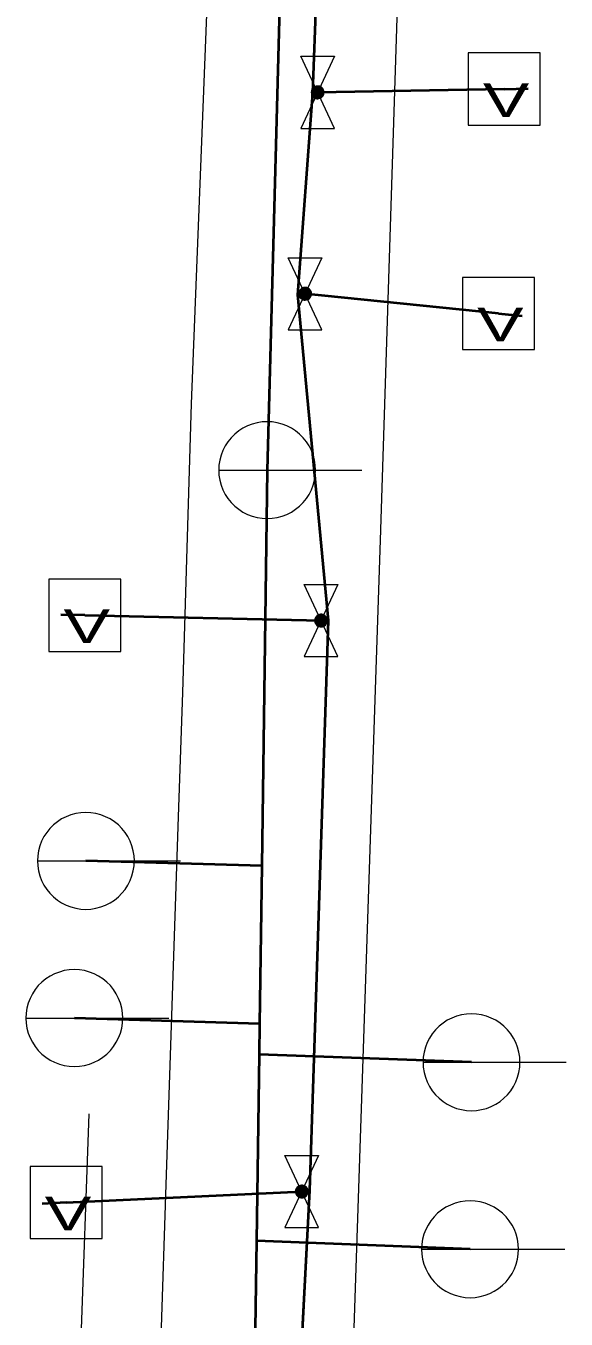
# Model space of a CAD drawing. Extents: x -968691 to -140888, y -1376050 to -879856.
# Drawn here: x -646122.08 to -646110.84, y -1062475.84 to -1062448.94 of the extents above; entities that cross this region are included whole.
import ezdxf
from ezdxf.enums import TextEntityAlignment as Align

# ---------------------------------------------------------------- set-up
doc = ezdxf.new("R2010")
doc.units = 0
doc.header["$LTSCALE"] = 4.8
doc.linetypes.add('DOTTED', pattern=[1.5, 0.3, -1.2])
doc.linetypes.add('LONG_DASHED', pattern=[7.5, 6, -1.5])
doc.layers.add('1', color=7, linetype='Continuous', lineweight=13)

msp = doc.modelspace()

# ---------------------------------------------------------------- hatches: boundary and pattern name
at = {"layer": '1'}
for points in [[(-646115.878, -1062450.32), (-646115.88, -1062450.296), (-646115.887, -1062450.273), (-646115.897, -1062450.251), (-646115.911, -1062450.232), (-646115.929, -1062450.215), (-646115.949, -1062450.202), (-646115.972, -1062450.193), (-646115.995, -1062450.189), (-646116.019, -1062450.188), (-646116.043, -1062450.192), (-646116.066, -1062450.2), (-646116.087, -1062450.212), (-646116.105, -1062450.228), (-646116.12, -1062450.247), (-646116.132, -1062450.268), (-646116.139, -1062450.291), (-646116.142, -1062450.315), (-646116.141, -1062450.339), (-646116.135, -1062450.362), (-646116.125, -1062450.384), (-646116.112, -1062450.404), (-646116.095, -1062450.421), (-646116.075, -1062450.435), (-646116.053, -1062450.445), (-646116.03, -1062450.451), (-646116.006, -1062450.452), (-646115.982, -1062450.449), (-646115.959, -1062450.442), (-646115.938, -1062450.431), (-646115.919, -1062450.416), (-646115.903, -1062450.397), (-646115.891, -1062450.377), (-646115.882, -1062450.354), (-646115.878, -1062450.33)], [(-646116.138, -1062454.51), (-646116.14, -1062454.486), (-646116.147, -1062454.463), (-646116.157, -1062454.441), (-646116.171, -1062454.422), (-646116.189, -1062454.405), (-646116.209, -1062454.392), (-646116.232, -1062454.383), (-646116.255, -1062454.379), (-646116.279, -1062454.378), (-646116.303, -1062454.382), (-646116.326, -1062454.39), (-646116.347, -1062454.402), (-646116.365, -1062454.418), (-646116.38, -1062454.437), (-646116.392, -1062454.458), (-646116.399, -1062454.481), (-646116.402, -1062454.505), (-646116.401, -1062454.529), (-646116.395, -1062454.552), (-646116.385, -1062454.574), (-646116.372, -1062454.594), (-646116.355, -1062454.611), (-646116.335, -1062454.625), (-646116.313, -1062454.635), (-646116.29, -1062454.641), (-646116.266, -1062454.642), (-646116.242, -1062454.639), (-646116.219, -1062454.632), (-646116.198, -1062454.621), (-646116.179, -1062454.606), (-646116.163, -1062454.587), (-646116.151, -1062454.567), (-646116.142, -1062454.544), (-646116.138, -1062454.52)], [(-646115.808, -1062461.31), (-646115.81, -1062461.286), (-646115.817, -1062461.263), (-646115.827, -1062461.241), (-646115.841, -1062461.222), (-646115.859, -1062461.205), (-646115.879, -1062461.192), (-646115.902, -1062461.183), (-646115.925, -1062461.179), (-646115.949, -1062461.178), (-646115.973, -1062461.182), (-646115.996, -1062461.19), (-646116.017, -1062461.202), (-646116.035, -1062461.218), (-646116.05, -1062461.237), (-646116.062, -1062461.258), (-646116.069, -1062461.281), (-646116.072, -1062461.305), (-646116.071, -1062461.329), (-646116.065, -1062461.352), (-646116.055, -1062461.374), (-646116.042, -1062461.394), (-646116.025, -1062461.411), (-646116.005, -1062461.425), (-646115.983, -1062461.435), (-646115.96, -1062461.441), (-646115.936, -1062461.442), (-646115.912, -1062461.439), (-646115.889, -1062461.432), (-646115.868, -1062461.421), (-646115.849, -1062461.406), (-646115.833, -1062461.387), (-646115.821, -1062461.367), (-646115.812, -1062461.344), (-646115.808, -1062461.32)], [(-646116.208, -1062473.19), (-646116.21, -1062473.166), (-646116.217, -1062473.143), (-646116.227, -1062473.121), (-646116.241, -1062473.102), (-646116.259, -1062473.085), (-646116.279, -1062473.072), (-646116.302, -1062473.063), (-646116.325, -1062473.059), (-646116.349, -1062473.058), (-646116.373, -1062473.062), (-646116.396, -1062473.07), (-646116.417, -1062473.082), (-646116.435, -1062473.098), (-646116.45, -1062473.117), (-646116.462, -1062473.138), (-646116.469, -1062473.161), (-646116.472, -1062473.185), (-646116.471, -1062473.209), (-646116.465, -1062473.232), (-646116.455, -1062473.254), (-646116.442, -1062473.274), (-646116.425, -1062473.291), (-646116.405, -1062473.305), (-646116.383, -1062473.315), (-646116.36, -1062473.321), (-646116.336, -1062473.322), (-646116.312, -1062473.319), (-646116.289, -1062473.312), (-646116.268, -1062473.301), (-646116.249, -1062473.286), (-646116.233, -1062473.267), (-646116.221, -1062473.247), (-646116.212, -1062473.224), (-646116.208, -1062473.2)]]:
    msp.add_hatch(color=256, dxfattribs=at).paths.add_polyline_path(points)

# ---------------------------------------------------------------- linework, layer by layer
at = {"layer": '1', "linetype": 'LONG_DASHED', "lineweight": 40}
for p, q in [((-646115.47, -1062433.81), (-646116.12, -1062450.33)), ((-646116.12, -1062450.33), (-646116.43, -1062454.53)), ((-646116.12, -1062450.33), (-646116.01, -1062450.32)), ((-646112.13, -1062450.25), (-646116.01, -1062450.32)), ((-646116.43, -1062454.53), (-646116.27, -1062454.51)), ((-646116.43, -1062454.53), (-646115.79, -1062461.31)), ((-646112.25, -1062454.92), (-646116.27, -1062454.51)), ((-646120.85, -1062461.2), (-646115.94, -1062461.31)), ((-646115.79, -1062461.31), (-646116.18, -1062473.17)), ((-646115.94, -1062461.31), (-646115.79, -1062461.31)), ((-646117.174, -1062466.412), (-646120.83, -1062466.31)), ((-646117.219, -1062469.7), (-646121.07, -1062469.58)), ((-646112.81, -1062470.5), (-646117.228, -1062470.338)), ((-646121.24, -1062473.42), (-646116.34, -1062473.19)), ((-646116.18, -1062473.17), (-646116.77, -1062484.57)), ((-646116.18, -1062473.17), (-646116.34, -1062473.19)), ((-646112.84, -1062474.39), (-646117.282, -1062474.217))]:
    msp.add_line(p, q, dxfattribs=at)
at = {"layer": '1', "lineweight": 35}
for p, q in [((-646115.47, -1062433.81), (-646116.12, -1062450.33)), ((-646116.12, -1062450.33), (-646116.43, -1062454.53)), ((-646116.43, -1062454.53), (-646115.79, -1062461.31)), ((-646115.79, -1062461.31), (-646116.18, -1062473.17)), ((-646116.18, -1062473.17), (-646116.77, -1062484.57))]:
    msp.add_line(p, q, dxfattribs=at)
at = {"layer": '1'}
for p, q in [((-646118.635, -1062456.797), (-646118.301, -1062448.324)), ((-646116.12, -1062450.33), (-646116.01, -1062450.32)), ((-646112.13, -1062450.25), (-646116.01, -1062450.32)), ((-646112.13, -1062450.25), (-646111.63, -1062450.241)), ((-646116.43, -1062454.53), (-646116.27, -1062454.51)), ((-646112.25, -1062454.92), (-646116.27, -1062454.51)), ((-646112.25, -1062454.92), (-646111.753, -1062454.971)), ((-646118.811, -1062462.804), (-646118.635, -1062456.797)), ((-646118.068, -1062458.18), (-646115.092, -1062458.18)), ((-646114.71, -1062459.64), (-646115.51, -1062483.63)), ((-646120.85, -1062461.2), (-646121.35, -1062461.189)), ((-646120.85, -1062461.2), (-646115.94, -1062461.31)), ((-646115.94, -1062461.31), (-646115.79, -1062461.31)), ((-646118.906, -1062465.392), (-646118.811, -1062462.804)), ((-646119.153, -1062472.835), (-646118.906, -1062465.392)), ((-646121.838, -1062466.31), (-646118.862, -1062466.31)), ((-646117.174, -1062466.412), (-646120.83, -1062466.31)), ((-646122.078, -1062469.58), (-646119.102, -1062469.58)), ((-646117.219, -1062469.7), (-646121.07, -1062469.58)), ((-646112.81, -1062470.5), (-646117.228, -1062470.338)), ((-646113.818, -1062470.5), (-646110.842, -1062470.5)), ((-646120.769, -1062471.574), (-646121.569, -1062494.426)), ((-646119.77, -1062491.16), (-646119.153, -1062472.835)), ((-646121.24, -1062473.42), (-646116.34, -1062473.19)), ((-646116.18, -1062473.17), (-646116.34, -1062473.19)), ((-646121.24, -1062473.42), (-646121.739, -1062473.443)), ((-646112.84, -1062474.39), (-646117.282, -1062474.217)), ((-646113.848, -1062474.39), (-646110.872, -1062474.39))]:
    msp.add_line(p, q, dxfattribs=at)
at = {"layer": '1', "linetype": 'DOTTED', "lineweight": 40}
for p, q in [((-646112.13, -1062450.25), (-646111.63, -1062450.241)), ((-646112.25, -1062454.92), (-646111.753, -1062454.971)), ((-646120.85, -1062461.2), (-646121.35, -1062461.189)), ((-646121.24, -1062473.42), (-646121.739, -1062473.443))]:
    msp.add_line(p, q, dxfattribs=at)
at = {"layer": '1'}
msp.add_lwpolyline([(-646113.81, -1062431.66), (-646114.114, -1062440.939), (-646114.71, -1062459.64)], dxfattribs=at)
at = {"layer": '1', "linetype": 'LONG_DASHED', "lineweight": 40}
for points in [[(-646116.721, -1062445.47), (-646117.06, -1062458.18), (-646117.174, -1062466.412), (-646117.219, -1062469.7), (-646117.228, -1062470.338), (-646117.282, -1062474.217)], [(-646117.282, -1062474.217), (-646117.5, -1062490), (-646113.72, -1062489.86)]]:
    msp.add_lwpolyline(points, dxfattribs=at)
at = {"layer": '1', "lineweight": 35}
for points in [[(-646116.721, -1062445.47), (-646117.06, -1062458.18), (-646117.174, -1062466.412), (-646117.219, -1062469.7), (-646117.228, -1062470.338), (-646117.282, -1062474.217)], [(-646117.282, -1062474.217), (-646117.5, -1062490), (-646113.72, -1062489.86)]]:
    msp.add_lwpolyline(points, dxfattribs=at)
at = {"layer": '1'}
for points in [[(-646116.36, -1062449.57), (-646115.66, -1062449.57), (-646116.36, -1062451.07), (-646115.66, -1062451.07)], [(-646112.88, -1062451), (-646111.38, -1062451), (-646111.38, -1062449.5), (-646112.88, -1062449.5)], [(-646115.878, -1062450.32), (-646115.88, -1062450.296), (-646115.887, -1062450.273), (-646115.897, -1062450.251), (-646115.911, -1062450.232), (-646115.929, -1062450.215), (-646115.949, -1062450.202), (-646115.972, -1062450.193), (-646115.995, -1062450.189), (-646116.019, -1062450.188), (-646116.043, -1062450.192), (-646116.066, -1062450.2), (-646116.087, -1062450.212), (-646116.105, -1062450.228), (-646116.12, -1062450.247), (-646116.132, -1062450.268), (-646116.139, -1062450.291), (-646116.142, -1062450.315), (-646116.141, -1062450.339), (-646116.135, -1062450.362), (-646116.125, -1062450.384), (-646116.112, -1062450.404), (-646116.095, -1062450.421), (-646116.075, -1062450.435), (-646116.053, -1062450.445), (-646116.03, -1062450.451), (-646116.006, -1062450.452), (-646115.982, -1062450.449), (-646115.959, -1062450.442), (-646115.938, -1062450.431), (-646115.919, -1062450.416), (-646115.903, -1062450.397), (-646115.891, -1062450.377), (-646115.882, -1062450.354), (-646115.878, -1062450.33)], [(-646116.62, -1062453.76), (-646115.92, -1062453.76), (-646116.62, -1062455.26), (-646115.92, -1062455.26)], [(-646113, -1062455.67), (-646111.5, -1062455.67), (-646111.5, -1062454.17), (-646113, -1062454.17)], [(-646116.138, -1062454.51), (-646116.14, -1062454.486), (-646116.147, -1062454.463), (-646116.157, -1062454.441), (-646116.171, -1062454.422), (-646116.189, -1062454.405), (-646116.209, -1062454.392), (-646116.232, -1062454.383), (-646116.255, -1062454.379), (-646116.279, -1062454.378), (-646116.303, -1062454.382), (-646116.326, -1062454.39), (-646116.347, -1062454.402), (-646116.365, -1062454.418), (-646116.38, -1062454.437), (-646116.392, -1062454.458), (-646116.399, -1062454.481), (-646116.402, -1062454.505), (-646116.401, -1062454.529), (-646116.395, -1062454.552), (-646116.385, -1062454.574), (-646116.372, -1062454.594), (-646116.355, -1062454.611), (-646116.335, -1062454.625), (-646116.313, -1062454.635), (-646116.29, -1062454.641), (-646116.266, -1062454.642), (-646116.242, -1062454.639), (-646116.219, -1062454.632), (-646116.198, -1062454.621), (-646116.179, -1062454.606), (-646116.163, -1062454.587), (-646116.151, -1062454.567), (-646116.142, -1062454.544), (-646116.138, -1062454.52)], [(-646117.06, -1062457.172), (-646117.165, -1062457.178), (-646117.269, -1062457.194), (-646117.371, -1062457.222), (-646117.47, -1062457.26), (-646117.564, -1062457.307), (-646117.652, -1062457.365), (-646117.734, -1062457.431), (-646117.809, -1062457.506), (-646117.875, -1062457.588), (-646117.933, -1062457.676), (-646117.98, -1062457.77), (-646118.018, -1062457.869), (-646118.046, -1062457.971), (-646118.062, -1062458.075), (-646118.068, -1062458.18), (-646118.062, -1062458.285), (-646118.046, -1062458.39), (-646118.018, -1062458.492), (-646117.98, -1062458.59), (-646117.933, -1062458.684), (-646117.875, -1062458.773), (-646117.809, -1062458.855), (-646117.734, -1062458.929), (-646117.652, -1062458.995), (-646117.564, -1062459.053), (-646117.47, -1062459.101), (-646117.371, -1062459.139), (-646117.269, -1062459.166), (-646117.165, -1062459.182), (-646117.06, -1062459.188), (-646116.955, -1062459.182), (-646116.85, -1062459.166), (-646116.748, -1062459.139), (-646116.65, -1062459.101), (-646116.556, -1062459.053), (-646116.467, -1062458.995), (-646116.385, -1062458.929), (-646116.311, -1062458.855), (-646116.245, -1062458.773), (-646116.187, -1062458.684), (-646116.139, -1062458.59), (-646116.101, -1062458.492), (-646116.074, -1062458.39), (-646116.058, -1062458.285), (-646116.052, -1062458.18), (-646116.058, -1062458.075), (-646116.074, -1062457.971), (-646116.101, -1062457.869), (-646116.139, -1062457.77), (-646116.187, -1062457.676), (-646116.245, -1062457.588), (-646116.311, -1062457.506), (-646116.385, -1062457.431), (-646116.467, -1062457.365), (-646116.556, -1062457.307), (-646116.65, -1062457.26), (-646116.748, -1062457.222), (-646116.85, -1062457.194), (-646116.955, -1062457.178)], [(-646121.6, -1062461.95), (-646120.1, -1062461.95), (-646120.1, -1062460.45), (-646121.6, -1062460.45)], [(-646116.29, -1062460.56), (-646115.59, -1062460.56), (-646116.29, -1062462.06), (-646115.59, -1062462.06)], [(-646115.808, -1062461.31), (-646115.81, -1062461.286), (-646115.817, -1062461.263), (-646115.827, -1062461.241), (-646115.841, -1062461.222), (-646115.859, -1062461.205), (-646115.879, -1062461.192), (-646115.902, -1062461.183), (-646115.925, -1062461.179), (-646115.949, -1062461.178), (-646115.973, -1062461.182), (-646115.996, -1062461.19), (-646116.017, -1062461.202), (-646116.035, -1062461.218), (-646116.05, -1062461.237), (-646116.062, -1062461.258), (-646116.069, -1062461.281), (-646116.072, -1062461.305), (-646116.071, -1062461.329), (-646116.065, -1062461.352), (-646116.055, -1062461.374), (-646116.042, -1062461.394), (-646116.025, -1062461.411), (-646116.005, -1062461.425), (-646115.983, -1062461.435), (-646115.96, -1062461.441), (-646115.936, -1062461.442), (-646115.912, -1062461.439), (-646115.889, -1062461.432), (-646115.868, -1062461.421), (-646115.849, -1062461.406), (-646115.833, -1062461.387), (-646115.821, -1062461.367), (-646115.812, -1062461.344), (-646115.808, -1062461.32)], [(-646120.83, -1062465.302), (-646120.935, -1062465.308), (-646121.039, -1062465.324), (-646121.141, -1062465.352), (-646121.24, -1062465.39), (-646121.334, -1062465.437), (-646121.422, -1062465.495), (-646121.504, -1062465.561), (-646121.579, -1062465.636), (-646121.645, -1062465.718), (-646121.703, -1062465.806), (-646121.75, -1062465.9), (-646121.788, -1062465.999), (-646121.816, -1062466.101), (-646121.832, -1062466.205), (-646121.838, -1062466.31), (-646121.832, -1062466.415), (-646121.816, -1062466.52), (-646121.788, -1062466.622), (-646121.75, -1062466.72), (-646121.703, -1062466.814), (-646121.645, -1062466.903), (-646121.579, -1062466.985), (-646121.504, -1062467.059), (-646121.422, -1062467.125), (-646121.334, -1062467.183), (-646121.24, -1062467.231), (-646121.141, -1062467.269), (-646121.039, -1062467.296), (-646120.935, -1062467.312), (-646120.83, -1062467.318), (-646120.725, -1062467.312), (-646120.62, -1062467.296), (-646120.518, -1062467.269), (-646120.42, -1062467.231), (-646120.326, -1062467.183), (-646120.237, -1062467.125), (-646120.155, -1062467.059), (-646120.081, -1062466.985), (-646120.015, -1062466.903), (-646119.957, -1062466.814), (-646119.909, -1062466.72), (-646119.871, -1062466.622), (-646119.844, -1062466.52), (-646119.828, -1062466.415), (-646119.822, -1062466.31), (-646119.828, -1062466.205), (-646119.844, -1062466.101), (-646119.871, -1062465.999), (-646119.909, -1062465.9), (-646119.957, -1062465.806), (-646120.015, -1062465.718), (-646120.081, -1062465.636), (-646120.155, -1062465.561), (-646120.237, -1062465.495), (-646120.326, -1062465.437), (-646120.42, -1062465.39), (-646120.518, -1062465.352), (-646120.62, -1062465.324), (-646120.725, -1062465.308)], [(-646121.07, -1062468.572), (-646121.175, -1062468.578), (-646121.279, -1062468.594), (-646121.381, -1062468.622), (-646121.48, -1062468.66), (-646121.574, -1062468.707), (-646121.662, -1062468.765), (-646121.744, -1062468.831), (-646121.819, -1062468.906), (-646121.885, -1062468.988), (-646121.943, -1062469.076), (-646121.99, -1062469.17), (-646122.028, -1062469.269), (-646122.056, -1062469.371), (-646122.072, -1062469.475), (-646122.078, -1062469.58), (-646122.072, -1062469.685), (-646122.056, -1062469.79), (-646122.028, -1062469.892), (-646121.99, -1062469.99), (-646121.943, -1062470.084), (-646121.885, -1062470.173), (-646121.819, -1062470.255), (-646121.744, -1062470.329), (-646121.662, -1062470.395), (-646121.574, -1062470.453), (-646121.48, -1062470.501), (-646121.381, -1062470.539), (-646121.279, -1062470.566), (-646121.175, -1062470.582), (-646121.07, -1062470.588), (-646120.965, -1062470.582), (-646120.86, -1062470.566), (-646120.758, -1062470.539), (-646120.66, -1062470.501), (-646120.566, -1062470.453), (-646120.477, -1062470.395), (-646120.395, -1062470.329), (-646120.321, -1062470.255), (-646120.255, -1062470.173), (-646120.197, -1062470.084), (-646120.149, -1062469.99), (-646120.111, -1062469.892), (-646120.084, -1062469.79), (-646120.068, -1062469.685), (-646120.062, -1062469.58), (-646120.068, -1062469.475), (-646120.084, -1062469.371), (-646120.111, -1062469.269), (-646120.149, -1062469.17), (-646120.197, -1062469.076), (-646120.255, -1062468.988), (-646120.321, -1062468.906), (-646120.395, -1062468.831), (-646120.477, -1062468.765), (-646120.566, -1062468.707), (-646120.66, -1062468.66), (-646120.758, -1062468.622), (-646120.86, -1062468.594), (-646120.965, -1062468.578)], [(-646112.81, -1062469.492), (-646112.915, -1062469.498), (-646113.019, -1062469.514), (-646113.121, -1062469.542), (-646113.22, -1062469.58), (-646113.314, -1062469.627), (-646113.402, -1062469.685), (-646113.484, -1062469.751), (-646113.559, -1062469.826), (-646113.625, -1062469.908), (-646113.683, -1062469.996), (-646113.73, -1062470.09), (-646113.768, -1062470.189), (-646113.796, -1062470.291), (-646113.812, -1062470.395), (-646113.818, -1062470.5), (-646113.812, -1062470.605), (-646113.796, -1062470.71), (-646113.768, -1062470.812), (-646113.73, -1062470.91), (-646113.683, -1062471.004), (-646113.625, -1062471.093), (-646113.559, -1062471.175), (-646113.484, -1062471.249), (-646113.402, -1062471.315), (-646113.314, -1062471.373), (-646113.22, -1062471.421), (-646113.121, -1062471.459), (-646113.019, -1062471.486), (-646112.915, -1062471.502), (-646112.81, -1062471.508), (-646112.705, -1062471.502), (-646112.6, -1062471.486), (-646112.498, -1062471.459), (-646112.4, -1062471.421), (-646112.306, -1062471.373), (-646112.217, -1062471.315), (-646112.135, -1062471.249), (-646112.061, -1062471.175), (-646111.995, -1062471.093), (-646111.937, -1062471.004), (-646111.889, -1062470.91), (-646111.851, -1062470.812), (-646111.824, -1062470.71), (-646111.808, -1062470.605), (-646111.802, -1062470.5), (-646111.808, -1062470.395), (-646111.824, -1062470.291), (-646111.851, -1062470.189), (-646111.889, -1062470.09), (-646111.937, -1062469.996), (-646111.995, -1062469.908), (-646112.061, -1062469.826), (-646112.135, -1062469.751), (-646112.217, -1062469.685), (-646112.306, -1062469.627), (-646112.4, -1062469.58), (-646112.498, -1062469.542), (-646112.6, -1062469.514), (-646112.705, -1062469.498)], [(-646116.69, -1062472.44), (-646115.99, -1062472.44), (-646116.69, -1062473.94), (-646115.99, -1062473.94)], [(-646121.99, -1062474.17), (-646120.49, -1062474.17), (-646120.49, -1062472.67), (-646121.99, -1062472.67)], [(-646116.208, -1062473.19), (-646116.21, -1062473.166), (-646116.217, -1062473.143), (-646116.227, -1062473.121), (-646116.241, -1062473.102), (-646116.259, -1062473.085), (-646116.279, -1062473.072), (-646116.302, -1062473.063), (-646116.325, -1062473.059), (-646116.349, -1062473.058), (-646116.373, -1062473.062), (-646116.396, -1062473.07), (-646116.417, -1062473.082), (-646116.435, -1062473.098), (-646116.45, -1062473.117), (-646116.462, -1062473.138), (-646116.469, -1062473.161), (-646116.472, -1062473.185), (-646116.471, -1062473.209), (-646116.465, -1062473.232), (-646116.455, -1062473.254), (-646116.442, -1062473.274), (-646116.425, -1062473.291), (-646116.405, -1062473.305), (-646116.383, -1062473.315), (-646116.36, -1062473.321), (-646116.336, -1062473.322), (-646116.312, -1062473.319), (-646116.289, -1062473.312), (-646116.268, -1062473.301), (-646116.249, -1062473.286), (-646116.233, -1062473.267), (-646116.221, -1062473.247), (-646116.212, -1062473.224), (-646116.208, -1062473.2)], [(-646112.84, -1062473.382), (-646112.945, -1062473.388), (-646113.049, -1062473.404), (-646113.151, -1062473.432), (-646113.25, -1062473.47), (-646113.344, -1062473.517), (-646113.432, -1062473.575), (-646113.514, -1062473.641), (-646113.589, -1062473.716), (-646113.655, -1062473.798), (-646113.713, -1062473.886), (-646113.76, -1062473.98), (-646113.798, -1062474.079), (-646113.826, -1062474.181), (-646113.842, -1062474.285), (-646113.848, -1062474.39), (-646113.842, -1062474.495), (-646113.826, -1062474.6), (-646113.798, -1062474.702), (-646113.76, -1062474.8), (-646113.713, -1062474.894), (-646113.655, -1062474.983), (-646113.589, -1062475.065), (-646113.514, -1062475.139), (-646113.432, -1062475.205), (-646113.344, -1062475.263), (-646113.25, -1062475.311), (-646113.151, -1062475.349), (-646113.049, -1062475.376), (-646112.945, -1062475.392), (-646112.84, -1062475.398), (-646112.735, -1062475.392), (-646112.63, -1062475.376), (-646112.528, -1062475.349), (-646112.43, -1062475.311), (-646112.336, -1062475.263), (-646112.247, -1062475.205), (-646112.165, -1062475.139), (-646112.091, -1062475.065), (-646112.025, -1062474.983), (-646111.967, -1062474.894), (-646111.919, -1062474.8), (-646111.881, -1062474.702), (-646111.854, -1062474.6), (-646111.838, -1062474.495), (-646111.832, -1062474.39), (-646111.838, -1062474.285), (-646111.854, -1062474.181), (-646111.881, -1062474.079), (-646111.919, -1062473.98), (-646111.967, -1062473.886), (-646112.025, -1062473.798), (-646112.091, -1062473.716), (-646112.165, -1062473.641), (-646112.247, -1062473.575), (-646112.336, -1062473.517), (-646112.43, -1062473.47), (-646112.528, -1062473.432), (-646112.63, -1062473.404), (-646112.735, -1062473.388)]]:
    msp.add_lwpolyline(points, close=True, dxfattribs=at)

# ---------------------------------------------------------------- texts
at = {"layer": '1', "width": 1.55}
for p in [(-646112.091, -1062450.829), (-646112.211, -1062455.499), (-646120.811, -1062461.779), (-646121.201, -1062473.999)]:
    msp.add_text('V', height=0.7, dxfattribs=at).set_placement(p, align=Align.CENTER)

doc.saveas('drawing.dxf')
